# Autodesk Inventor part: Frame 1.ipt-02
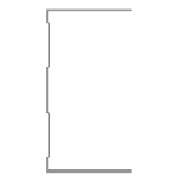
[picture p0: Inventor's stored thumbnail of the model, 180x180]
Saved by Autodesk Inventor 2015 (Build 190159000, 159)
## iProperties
IsCustomPart: 1
Created: 2015-04
Part Number: Frame 1.ipt-02
Material: Aluminum 6061
Description: Kévin Novo
Document SubType Name: Modeling
Standard: Kevin
Designer: suporte
Standards Organization: Kevin
Language: en-US
Size Designation: (Unnamed 2)
Categories: <MemberInstance><Categories><Category DisplayName="Structural Shapes" InternalName="089c4875-fa83-4c05-b084-43b9cc11f5ed" Mnemonic="GRDR"><CategoryParameter Dis
Density: 2.7 g/cm^3
Appearance: Aluminum - Flat
_CCFamilyMember: 2
_CCFamilyDisplayName: Kévin - Kévin Novo
_FrameMemberDoc: Frame Member File
_Version: 15.0.0
_GetPNFromCC: 1
G_W: 50,000 mm
G_H: 75,000 mm
G_L: 1054,820 mm
+C6D07C4E-F784-4905-9E85-D001DAC4732C+CUTDETAIL2: Miter 67,49 deg
Author: suporte
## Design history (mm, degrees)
node "Start Plane"
node "End Plane"
sketch "Sketch"
  geometry: L1 (24.7, 37.5)-(24.7, 36.9); L2 (24.7, 36.9)-(-24.7, 36.9); L3 (-24.7, -36.9)-(24.7, -36.9); L4 (24.7, -36.9)-(24.7, -37.5); L5 (24.7, -37.5)-(-25.3, -37.5); L6 (-25.3, 37.5)-(24.7, 37.5); L7 (-24.7, 36.9)-(-24.7, 31.9); L8 (-24.7, 31.9)-(-23.3, 30.5); L9 (-23.3, 30.5)-(-23.3, 10.934); L10 (-23.3, 10.934)-(-24.7, 9.534); L11 (-24.7, 9.534)-(-24.7, -9.534); L12 (-24.7, -9.534)-(-23.3, -10.934); L13 (-23.3, -10.934)-(-23.3, -30.5); L14 (-23.3, -30.5)-(-24.7, -31.9); L15 (-24.7, -31.9)-(-24.7, -36.9); L16 (-25.3, -37.5)-(-25.3, -31.651); L17 (-25.3, -31.651)-(-23.9, -30.251); L18 (-23.9, -30.251)-(-23.9, -11.183); L19 (-23.9, -11.183)-(-25.3, -9.783); L20 (-25.3, -9.783)-(-25.3, 9.783); L21 (-25.3, 9.783)-(-23.9, 11.183); L22 (-23.9, 11.183)-(-23.9, 30.251); L23 (-23.9, 30.251)-(-25.3, 31.651); L24 (-25.3, 31.651)-(-25.3, 37.5); L25 (-25.3, 0)-(30.37, 0); 3 further points
  constraints: 50 end point, 10 point on line, 9 parallel, 5 perpendicular, 4 equal length, 3 midpoint, 3 vertical, 2 vertical alignment, 1 collinear, 1 horizontal, 1 horizontal alignment
  dimensions: "d3" = 0.6 distance of L1.start L1.end (= d6); "d5" = 75 distance between parallel lines of L5 L6; "d6" = 0.6 distance between parallel lines of L24 L7 (= d8); "d7" = 0.6 distance between parallel lines of L8 L23 (= d8); "d8" = 0.6 distance between parallel lines of L22 L9 (= d12); "Espessura" = 0.6 distance between parallel lines of L17 L14; "d10" = 0.6 distance between parallel lines of L13 L18 (= Espessura); "d11" = 0.6 distance between parallel lines of L12 L19 (= Espessura); "d12" = 0.6 distance between parallel lines of L21 L10 (= d11); "d13" = 5 distance of L2.end L7.end; "d15" = 135 deg angle of L9 L8; "d16" = 2 distance between parallel lines of L24 L9; "d17" = 50 distance of L6.start L1.start
extrude "Body" join sketch "Sketch" stored distance "d24" = 0.13; taper "d25" = 0 deg
node "Driven Length"
  sketch "Sketch10"
    geometry: L1 (0, 0)-(10, 0) reference
    constraints: 2 end point, 1 horizontal
  workplane "Work Plane7"
  sketch "Sketch11"
    geometry: L1 (-2, 0)-(12, 0) reference; L2 (-2, 1054.82)-(12, 1054.82) reference
    dimensions: "d27" = 1054.81978 distance between parallel lines of L1 L2 (derived)
workplane "Work Plane9"
split "Split2"
body "Solid1"
other parameters: "tamanho" = 1018.55826, "G_OFFSET_START" = 0 [user parameter; used in 1 equation term], "G_OFFSET_END" = 36.26152 [user parameter; used in 1 equation term], "d22" = 0 (computed from G_OFFSET_START), "d23" = 1054.81978 (= tamanho + G_OFFSET_END), "G_L" = 1054.81978 (= d27) [user parameter], "d34" = 90 deg
